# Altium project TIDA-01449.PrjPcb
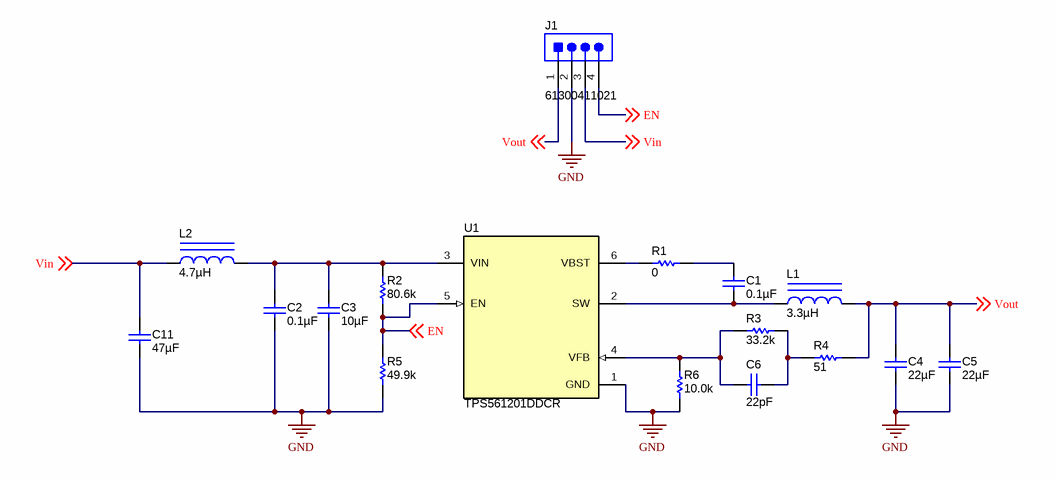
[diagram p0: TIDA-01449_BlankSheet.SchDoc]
TID: N/A; TechSupport: http://www.ti.com/support; SCH_Rev: E1; PRJ_Title: Change in menu Project|Project Options|Parameters; PRJ_Number: TIDA-01449; PRJ_Engineer: Stauder; PRJ_Customer: TIDesign; PCB_Rev: E1; PCB_Layout: Stauder; CopyrightYear: 2017
1 sheet, 17 parts. Net scope: global (net labels, ports and power ports of the same name join across sheets).
Board file: TIDA-01449_PCB.PcbDoc

## Sheet TIDA-01449_BlankSheet.SchDoc
size 431 x 279 mm; Date: Not shown in title block; ApprovedBy: Not shown in title block; CheckedBy: Not shown in title block; Author: Not shown in title block; CompanyName: Not shown in title block; Engineer: Not shown in title block; Organization: Not shown in title block; Address1: Not shown in title block; Address2: Not shown in title block; Address3: Not shown in title block; Address4: Not shown in title block; DocumentNumber: 1; Revision: Use project parameter SCH_Rev; SheetNumber: 2; SheetTotal: 3; PageSetup: Record=PageOptions¦CenterHorizontal=True¦CenterVertical=True¦PrintScale=1.00¦XCorrection=1.00¦YCorrection=1.00¦PrintKind=0¦BorderSize=5000000¦LeftOffset=0¦BottomOffset=0¦Orientation=2¦PaperLength=1000¦PaperWidth=1000¦Scale=100¦PaperSource=15¦PrintQuality=600¦MediaType=1¦DitherType=10¦PaperKind=Letter¦PrintScaleMode=1

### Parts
C1  ValueDisplayed: 0.1µF  [0603]  (hidden comment: GRM188R70J104KA01D)
C2  ValueDisplayed: 0.1µF  [0603]  (hidden comment: 885012206071)
C3  ValueDisplayed: 10µF  [1206]  (hidden comment: GMK316AB7106KL)
C4  ValueDisplayed: 22µF  [0805_HV]  (hidden comment: GRM21BZ71A226ME15L)
C5  ValueDisplayed: 22µF  [0805_HV]  (hidden comment: GRM21BZ71A226ME15L)
C6  ValueDisplayed: 22pF  [0603]  (hidden comment: GRM1885C1H220JA01D)
C11  ValueDisplayed: 47µF  [1206_190L]  (hidden comment: C3216X5R1E476M160AC)
J1  61300411021  [Wurth_61300411021]
L1  ValueDisplayed: 3.3µH  [ABG06A45]  (hidden comment: ABG06A45M3R3)
L2  ValueDisplayed: 4.7µH  [ABG03A15]  (hidden comment: ABG03A15M4R7)
R1  ValueDisplayed: 0  [0603]  (hidden comment: CRCW06030000Z0EA)
R2  ValueDisplayed: 80.6k  [0603]  (hidden comment: CRCW060380K6FKEA)
R3  ValueDisplayed: 33.2k  [0603]  (hidden comment: CRCW060333K2FKEA)
R4  ValueDisplayed: 51  [0603]  (hidden comment: CRCW060351R0JNEA)
R5  ValueDisplayed: 49.9k  [0603]  (hidden comment: CRCW060349K9FKEA)
R6  ValueDisplayed: 10.0k  [0603]  (hidden comment: RCG060310K0FKEA)
U1  TPS561201DDCR  [DDC0006A_N]

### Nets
GND: C2.2 C3.2 C4.2 C5.2 C11.2 J1.2 R5.1 R6.1 U1.1(GND)
EN: J1.4 R2.1 R5.2 U1.5(EN) ; off-sheet EN
Vin: C11.1 J1.3 L2.1 ; off-sheet Vin
Vout: C4.1 C5.1 J1.1 L1.2 R4.2 ; off-sheet Vout
NetC1_1: C1.1 R1.2
NetC1_2: C1.2 L1.1 U1.2(SW)
NetC2_1: C2.1 C3.1 L2.2 R2.2 U1.3(VIN)
NetC6_1: C6.1 R3.2 R4.1
NetC6_2: C6.2 R3.1 R6.2 U1.4(VFB)
NetR1_1: R1.1 U1.6(VBST)

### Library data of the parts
C1 = GRM188R70J104KA01D: CAP, CERM, 0.1 µF, 6.3 V, +/- 10%, X7R, 0603; Manufacturer: MuRata; Polarized: N; CompType: Capacitor; Value: 0.1uF; U/M: EA; Cap_F: 0.0000001; Tolerance_%: 10; Value1: Unknown; VDC_V: 6.3; Value2: 6.3V; TaMin_C: -55; TaMax_C: 125; AEC Category: Q200
C2 = 885012206071: CAP, CERM, 0.1 µF, 25 V, +/- 10%, X7R, 0603; Manufacturer: Wurth Elektronik; Polarized: N; CompType: Capacitor; Value: 0.1uF; U/M: EA; Cap_F: 0.0000001; Tolerance_%: 10; Value1: Unknown; VDC_V: 25; Value2: 25V; TaMin_C: -55; TaMax_C: 125; AEC Category: Q200
C3 = GMK316AB7106KL: CAP, CERM, 10 µF, 35 V, +/- 10%, X7R, 1206; Manufacturer: Taiyo Yuden; Polarized: N; CompType: Capacitor; Value: 10uF; U/M: EA; Cap_F: 0.00001; Tolerance_%: 10; Value1: Unknown; VDC_V: 35; Value2: 35V; TaMin_C: -55; TaMax_C: 125; AEC Category: Q200
C4 C5 = GRM21BZ71A226ME15L: CAP, CERM, 22 µF, 10 V, +/- 20%, X7R, 0805; Manufacturer: MuRata; Polarized: N; CompType: Capacitor; Value: 22uF; U/M: EA; Cap_F: 0.000022; Tolerance_%: 20; Value1: Unknown; VDC_V: 10; Value2: 10V; TaMin_C: -55; TaMax_C: 125; Cap_Case: 0805; AEC Category: Q200
C6 = GRM1885C1H220JA01D: CAP, CERM, 22 pF, 50 V, +/- 5%, C0G/NP0, 0603; Manufacturer: MuRata; Polarized: N; CompType: Capacitor; Value: 22pF; U/M: EA; Cap_F: 0.000000000022; Tolerance_%: 5; Value1: Unknown; VDC_V: 50; Value2: 50V; TaMin_C: -55; TaMax_C: 125; AEC Category: Q200
C11 = C3216X5R1E476M160AC: CAP, CERM, 47 µF, 25 V,+/- 20%, X5R, 1206; Manufacturer: TDK; Polarized: N; CompType: Capacitor; Value: 47uF; U/M: EA; Cap_F: 0.000047; Tolerance_%: 20; VDC_V: 25; Value2: 25V; TaMin_C: -55; TaMax_C: 85; Cap_Case: 1206; SizeArea_mm2: 5.12; SizeAreaWB_mm2: 10.92; SizeX_mm: 3.2; SizeY_mm: 1.6; SizeZ_mm: 1.9; AEC Category: Q200; Green_Lifecycle: Active; Green_REACh: Passed
J1 = 61300411021: Header, 2.54 mm, 4x1, Gold, R/A, TH; Manufacturer: Wurth Elektronik; SymbolCreator: a0412235; Pitch_mm: 2.54; Gender: Male; Shrouded: N; Row_Count: 1
L1 = ABG06A45M3R3: Inductor, 3.3 µH, 3.91 A, 0.026 ohm, SMD; Manufacturer: Coilank; Value: 3.3uH; Ind_H: 3.3E-6; Imax_A: 3.91; Irms: 3.81A @ 40C rise; Isat: 6.08A @ 35% inductance drop; DCR_ohm: 0.026; Value2: 3.91A; AEC Category: Q200; AEC Qualified: N; SizeAreaWB_mm2: 64; SizeArea_mm2: 36; SizeX_mm: 6; SizeZ_mm: 4.5
L2 = ABG03A15M4R7: Inductor, 4.7 µH, 1.12 A, 0.12 ohm, SMD; Manufacturer: Coilank; Value: 4.7uH; Ind_H: 4.7E-6; Imax_A: 1.12; Irms: 1.12A @ 40C rise; Isat: 1.13A @ 35% inductance drop; DCR_ohm: 0.12; Value2: 1.12A; AEC Category: Q200; AEC Qualified: N; SizeAreaWB_mm2: 16; SizeArea_mm2: 9; SizeX_mm: 3; SizeZ_mm: 1.5
R1 = CRCW06030000Z0EA: RES, 0, 5%, 0.1 W, 0603; Manufacturer: Vishay-Dale; CompType: Resistor; Value: 0; Value_Code: 0000; Tolerance_%: 5; Power_W: 0.1; Value2: 0.1W; VDC_V: 75; TempCo: 200 ppm/C; EIA_Code: E24; U/M: EA; AEC Category: Q200
R2 = CRCW060380K6FKEA: RES, 80.6 k, 1%, 0.1 W, 0603; Manufacturer: Vishay-Dale; CompType: Resistor; Value: 80.6k; Res_ohm: 80600; Value_Code: 80k6; Tolerance_%: 1; Power_W: 0.1; Value2: 0.1W; VDC_V: 75; TempCo: 100 ppm/C; EIA_Code: E96; U/M: EA; AEC Category: Q200; SizeArea_mm2: 1.28; SizeX_mm: 1.6; SizeY_mm: 0.8; Green_Lifecycle: Active; Green_REACh: Passed
R3 = CRCW060333K2FKEA: RES, 33.2 k, 1%, 0.1 W, 0603; Manufacturer: Vishay-Dale; CompType: Resistor; Value: 33.2k; Res_ohm: 33200; Value_Code: 33k2; Tolerance_%: 1; Power_W: 0.1; Value2: 0.1W; VDC_V: 75; TempCo: 100 ppm/C; EIA_Code: E96; U/M: EA; AEC Category: Q200; SizeArea_mm2: 1.28; SizeX_mm: 1.6; SizeY_mm: 0.8; Green_Lifecycle: Active; Green_REACh: Passed
R4 = CRCW060351R0JNEA: RES, 51, 5%, 0.1 W, 0603; Manufacturer: Vishay-Dale; CompType: Resistor; Value: 51; Value_Code: 51R0; Tolerance_%: 5; Power_W: 0.1; Value2: 0.1W; VDC_V: 75; TempCo: 200 ppm/C; EIA_Code: E24; U/M: EA; AEC Category: Q200
R5 = CRCW060349K9FKEA: RES, 49.9 k, 1%, 0.1 W, 0603; Manufacturer: Vishay-Dale; CompType: Resistor; Value: 49.9k; Res_ohm: 49900; Value_Code: 49k9; Tolerance_%: 1; Power_W: 0.1; Value2: 0.1W; VDC_V: 75; TempCo: 100 ppm/C; EIA_Code: E96; U/M: EA; AEC Category: Q200; SizeArea_mm2: 1.28; SizeX_mm: 1.6; SizeY_mm: 0.8; Green_Lifecycle: Active; Green_REACh: Passed
R6 = RCG060310K0FKEA: RES, 10.0 k, 1%, 0.1 W, 0603; Manufacturer: Vishay Draloric; CompType: Resistor; Value: 10.0k; Res_ohm: 10000; Value_Code: 10k0; Tolerance_%: 1; Power_W: 0.1; Value2: 0.1W; VDC_V: 75; TempCo: 100 ppm/C; EIA_Code: E96; U/M: EA; AEC Category: Q200; AEC Qualified: N; SizeArea_mm2: 1.28; SizeX_mm: 1.6; SizeY_mm: 0.8
U1 = TPS561201DDCR: 4.5-V to 17-V Input, 2-A Synchronous Step-Down Voltage Regulator, DDC0006A (SOT-23-T-6); Alternate PartNumber: TPS561201DDCT; Manufacturer: Texas Instruments; SymbolCreator: a0411947; CompType: IC; U/M: EA; SizeArea_mm2: 4.8675; SizeAreaWB_mm2: 10.4675; SizeX_mm: 1.65; SizeY_mm: 2.95; SizeZ_mm: 0.87

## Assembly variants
001: not fitted FID1 FID2 FID3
